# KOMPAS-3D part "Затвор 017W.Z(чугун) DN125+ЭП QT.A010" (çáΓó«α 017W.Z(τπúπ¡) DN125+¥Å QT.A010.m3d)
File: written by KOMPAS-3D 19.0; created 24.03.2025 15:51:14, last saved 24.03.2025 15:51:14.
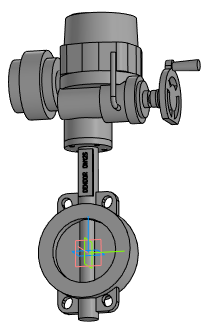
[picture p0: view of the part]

Document properties: Полное имя файла: Затвор 017W.Z(чугун) DN125+ЭП QT.A010.a3d

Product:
- Part/product: Затвор 017W.Z(чугун) DN125+ЭП QT.A010
    Масса: 45.8188

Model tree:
1. Операция без истории:1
